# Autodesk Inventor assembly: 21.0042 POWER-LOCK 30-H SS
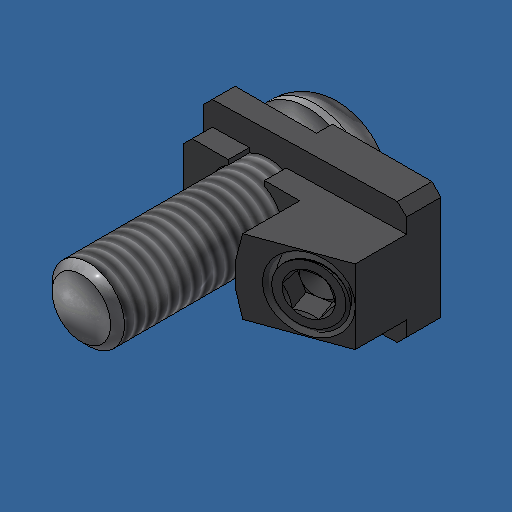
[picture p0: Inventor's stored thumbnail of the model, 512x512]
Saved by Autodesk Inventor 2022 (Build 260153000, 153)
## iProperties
Created: 2021-11
Part Number: 21.0042 POWER-LOCK 30-H SS
Document SubType Name: Assembly
Designer: amoles
Author: amoles
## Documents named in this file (4)
- L:\INVENTOR LIBRARIES\PARTS LIBRARY\30 SERIES\21.0042 POWER-LOCK 30-H SS.iam
- L:\INVENTOR LIBRARIES\PARTS LIBRARY\30 SERIES\SUBCOMPONENTS\21.0042 POWER-LOCK 30 BODY.ipt
- L:\INVENTOR LIBRARIES\PARTS LIBRARY\FASTENING ELEMENTS\SCREWS OTHER\21.1189_1 POWER-LOCK SCREW SS.ipt
- L:\INVENTOR LIBRARIES\PARTS LIBRARY\FASTENING ELEMENTS\SET SCREWS\21.1598_1 M8X12 SET SCREW FLAT POINT SS.ipt
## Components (3 placed, 3 different names)
1. 21.0042/1 POWER-LOCK 30 BODY SS:1 — Mate:1, Flush:1, Mate:2, Insert:1, Mate:3, Flush:2
2. 21.1189_1 POWER-LOCK SCREW SS:1 — Insert:1
3. 21.1598_1 M8X12 SET SCREW FLAT POINT SS:1 — Mate:3, Flush:2
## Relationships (6: Mate 3, Flush 2, Insert 1)
- Mate:1: 21.0042/1 POWER-LOCK 30 BODY SS:1
- Flush:1: 21.0042/1 POWER-LOCK 30 BODY SS:1
- Mate:2: 21.0042/1 POWER-LOCK 30 BODY SS:1
- Insert:1: 21.0042/1 POWER-LOCK 30 BODY SS:1 ↔ 21.1189_1 POWER-LOCK SCREW SS:1
- Mate:3: 21.0042/1 POWER-LOCK 30 BODY SS:1 ↔ 21.1598_1 M8X12 SET SCREW FLAT POINT SS:1
- Flush:2: 21.0042/1 POWER-LOCK 30 BODY SS:1 ↔ 21.1598_1 M8X12 SET SCREW FLAT POINT SS:1
